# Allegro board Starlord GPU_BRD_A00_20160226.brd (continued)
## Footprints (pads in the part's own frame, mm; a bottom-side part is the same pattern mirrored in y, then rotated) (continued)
SOT23-2D4-312H44
  custom 0.191x0.191 smd: 1(-0.984,-0.953) 2(0.984,-0.953) 3(0,0.953)
SOT23-2D4-312H48
  custom 0.191x0.191 smd: 1(-0.984,-0.953) 2(0.984,-0.953) 3(0,0.953)
SOT23DGS2D4H44
  custom 0.191x0.191 smd: D(0,0.953) G(-0.984,-0.953) S(0.984,-0.953)
SOT-363H44
  rect 0.406x1.016 smd: 1(-0.65,-0.94) 2(0,-0.94) 3(0.65,-0.94) 4(0.65,0.94) 5(0,0.94) 6(-0.65,0.94)
STFSR158R113H62
  round 0.254 hole 2.87 unplated: (0,0)
  custom 1.003x1.003 smd: 1(0,-1.822)
TPAD14-OP
  round 0.356 smd: 1(0,0)
unnamed
  round 1.016 smd: (0,0)
XBGCB5008
  round 0.254 hole 2.718 unplated: (0,0)
  round 0.254 hole 0.711 unplated: (5.143,-2.145) (5.143,2.105)
  rect 0.813x0.508 smd: A1(-3.805,2.165) A2(-3.805,1.365) A3(-3.805,0.565) A4(-3.805,-0.235) A5(-3.805,-1.035) A6(-3.805,-1.835) B1(-2.205,2.165) B2(-2.205,1.365) B3(-2.205,0.565) B4(-2.205,-0.235) B5(-2.205,-1.035) B6(-2.205,-1.835) C1(2.595,2.165) C2(2.595,1.365) C3(2.595,0.565) C4(2.595,-0.235) C5(2.595,-1.035) C6(2.595,-1.835) D2(4.195,1.365) D3(4.195,0.565) D4(4.195,-0.235) D5(4.195,-1.035) P1(-0.605,2.165) P2(0.995,2.165) P3(-0.605,-1.835) P4(0.995,-1.835)
  rect 0.762x0.508 smd: D1(4.169,2.165) D6(4.169,-1.835)
  custom 1.124x1.124 smd: N1(-1.905,0)
XBGCB5009
  round 0.254 hole 0.711 unplated: (-5.325,-3.465) (0,3.34)
  round 0.254 hole 2.718 unplated: (0,0)
  rect 0.813x0.356 smd: A1(-4.15,2.845) A2(-4.15,2.245) A3(-4.15,1.645) A4(-4.15,1.045) A5(-4.15,0.445) A6(-4.15,-0.155) A7(-4.15,-0.755) A8(-4.15,-1.355) A9(-4.15,-1.955) A10(-4.15,-2.555) B1(-2.45,2.845) B2(-2.45,2.245) B3(-2.45,1.645) B4(-2.45,1.045) B5(-2.45,0.445) B6(-2.45,-0.155) B7(-2.45,-0.755) B8(-2.45,-1.355) B9(-2.45,-1.955) B10(-2.45,-2.555) C2(-0.82,2.245) C9(-0.82,-1.955) C10(-0.82,-2.555) D1(0.87,2.845) D2(0.87,2.245) D9(0.87,-1.955) D10(0.87,-2.555) E1(2.45,2.845) E2(2.45,2.245) E3(2.45,1.645) E4(2.45,1.045) E5(2.45,0.445) E6(2.45,-0.155) E7(2.45,-0.755) E8(2.45,-1.355) E9(2.45,-1.955) E10(2.45,-2.555) F1(4.15,2.845) F2(4.15,2.245) F3(4.15,1.645) F4(4.15,1.045) F5(4.15,0.445) F6(4.15,-0.155) F7(4.15,-0.755) F8(4.15,-1.355) F9(4.15,-1.955) F10(4.15,-2.555)
  rect 0.762x0.356 smd: C1(-0.846,2.845)
  custom 1.124x1.124 smd: N1(-1.905,0)

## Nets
3V3_AON_CT_2: C8306.1 U8301.10
3V3_AON_S0: C7315.1 C7316.1 C7324.1 C7704.1 C7735.1 C7736.1 C8301.1 GPU1.AA8 GPU1.AA9 GPU1.AB8 GPU1.G10 GPU1.G12 PR8203.1 PR8258.1 PR8304.1 PR8311.1 PR8316.1 Q7301.G Q7602.2 Q7606.G R7303.2 R7312.1 R7609.1 R7612.2 R7614.1 R7617.1 R7619.1 R7625.1 R7628.1 R7631.1 R7633.1 R7643.2 R7645.1 R7649.2 R7657.1 R8301.1 RN7601.3(B) RN7601.4(B) RN7604.1(A) RN7604.2(A) RN7605.1(A) RN7605.2(A) U7301.5 U8301.8 U8301.9
3V3_AON_S0_DISCHG: PQ8306.3 PR8316.2
5V_S0: GPU2.P2 PR8223.1 U8301.4
GND: C7310.2 C7312.2 C7315.2 C7316.2 C7317.2 C7318.2 C7319.2 C7323.2 C7324.2 C7326.2 C7501.2 C7502.2 C7505.2 C7506.2 C7507.2 C7513.2 C7514.2 C7517.2 C7518.2 C7520.2 C7525.2 C7601.2 C7602.2 C7603.2 C7604.2 C7605.2 C7606.2 C7607.1 C7608.1 C7609.2 C7610.2 C7701.2 C7702.2 C7703.2 C7704.2 C7708.2 C7709.2 C7710.2 C7711.2 C7712.2 C7713.2 C7714.2 C7717.2 C7719.2 C7720.2 C7721.2 C7722.2 C7723.2 C7724.2 C7725.2 C7726.2 C7728.2 C7729.2 C7730.2 C7731.2 C7732.2 C7734.2 C7735.2 C7736.2 C7801.1 C7802.2 C7803.2 C7804.2 C7805.2 C7806.2 C7807.2 C7808.2 C7809.2 C7810.2 C7811.2 C7812.2 C7813.2 C7814.2 C7815.2 C7816.2 C7817.2 C7818.2 C7819.2 C7820.2 C7821.2 C7822.2 C7823.2 C7824.2 C7825.2 C7826.2 C7901.1 C7902.2 C7903.2 C7904.2 C7905.2 C7906.2 C7907.2 C7908.2 C7909.2 C7910.2 C7911.2 C7912.2 C7913.2 C7914.2 C7915.2 C7916.2 C7917.2 C7918.2 C7919.2 C7920.2 C7921.2 C7922.2 C7923.2 C7924.2 C7925.2 C7926.2 C8301.2 C8302.2 C8304.2 C8305.2 C8306.2 C8307.2 C8308.1 C8309.2 C8310.2 EC9701.2 EC9702.2 EC9703.2 EC9704.2 EC9705.2 EC9706.2 GPU1.A2 GPU1.A26 GPU1.AA7 GPU1.AB7 GPU1.AB11 GPU1.AB14 GPU1.AB17 GPU1.AB20 GPU1.AB24 GPU1.AC2 GPU1.AC5 GPU1.AC8 GPU1.AC22 GPU1.AC26 GPU1.AD12 GPU1.AD13 GPU1.AD15 GPU1.AD16 GPU1.AD18 GPU1.AD19 GPU1.AD21 GPU1.AD22 GPU1.AE11 GPU1.AE14 GPU1.AE17 GPU1.AE20 GPU1.AF1 GPU1.AF5 GPU1.AF8 GPU1.AF11 GPU1.AF14 GPU1.AF17 GPU1.AF20 GPU1.AF23 GPU1.AG2 GPU1.AG26 GPU1.B1 GPU1.B5 GPU1.B8 GPU1.B11 GPU1.B14 GPU1.B17 GPU1.B20 GPU1.B23 GPU1.B27 GPU1.E2 GPU1.E5 GPU1.E8 GPU1.E11 GPU1.E14 GPU1.E17 GPU1.E20 GPU1.E22 GPU1.E25 GPU1.H2 GPU1.H5 GPU1.H23 GPU1.H25 GPU1.K11 GPU1.K13 GPU1.K15 GPU1.K17 GPU1.L2 GPU1.L5 GPU1.L10 GPU1.L12 GPU1.L14 GPU1.L16 GPU1.L18 GPU1.L23 GPU1.L25 GPU1.M11 GPU1.M13 GPU1.M15 GPU1.M17 GPU1.N10 GPU1.N12 GPU1.N14 GPU1.N16 GPU1.N18 GPU1.P2 GPU1.P5 GPU1.P11 GPU1.P13 GPU1.P15 GPU1.P17 GPU1.P23 GPU1.P26 GPU1.R10 GPU1.R12 GPU1.R14 GPU1.R16 GPU1.R18 GPU1.T11 GPU1.T13 GPU1.T15 GPU1.T17 GPU1.U2 GPU1.U5 GPU1.U10 GPU1.U12 GPU1.U14 GPU1.U16 GPU1.U18 GPU1.U23 GPU1.U26 GPU1.V11 GPU1.V13 GPU1.V15 GPU1.V17 GPU1.Y2 GPU1.Y5 GPU1.Y23 GPU1.Y26 GPU2.C1 GPU2.C2 GPU2.C3 GPU2.C4 GPU2.C5 GPU2.C6 GPU2.D1 GPU2.D2 GPU2.D3 GPU2.D4 GPU2.D5 GPU2.D6 GPU3.A2 GPU3.A5 GPU3.A8 GPU3.B1 GPU3.B4 GPU3.B7 GPU3.B10 GPU3.E1 GPU3.E4 GPU3.E7 GPU3.E10 GPU3.F2 GPU3.F5 GPU3.F8 H1.1 H2.1 H3.1 H4.1 H5.1 PC8202.1 PC8203.1 PC8205.2 PC8206.2 PC8207.2 PC8208.2 PC8209.2 PC8210.2 PC8212.2 PC8213.2 PC8214.2 PC8215.2 PC8217.2 PC8218.2 PC8220.1 PC8221.1 PC8222.2 PC8224.2 PC8225.1 PC8226.1 PC8301.2 PC8302.2 PC8303.2 PC8304.2 PC8306.2 PC8307.2 PC8309.2 PC8310.2 PC8311.2 PC8313.2 PC8314.2 PC8315.2 PC8316.2 PC8317.2 PC8318.2 PC8320.2 PC8321.2 PQ8301.1 PQ8301.4 PQ8305.1 PQ8305.4 PQ8306.1 PQ8306.4 PQ8307.1 PQ8307.4 PQ8308.1 PQ8308.4 PR8213.2 PR8224.2 PR8259.2 PR8302.2 PR8313.2 PR8323.1 PR8326.2 PT8206.2 PT8207.2 PT8208.2 PU8201.21 PU8202.5 PU8202.6 PU8202.7 PU8204.5 PU8204.6 PU8204.7 PU8206.5 PU8206.6 PU8206.7 PU8208.5 PU8208.6 PU8208.7 PU8301.11 PU8302.7 PU8302.8 PU8302.18 PU8302.21 Q7801.S Q7901.S R7301.2 R7302.2 R7306.2 R7506.2 R7507.1 R7518.2 R7520.1 R7521.1 R7601.2 R7602.2 R7606.2 R7607.1 R7608.2 R7610.2 R7611.2 R7615.2 R7616.2 R7621.2 R7622.2 R7624.2 R7626.2 R7627.2 R7629.2 R7632.2 R7637.2 R7807.2 R7808.2 R7809.2 R7810.1 R7811.1 R7813.2 R7901.2 R7904.2 R7909.1 R7911.1 R7912.2 R7913.2 R8304.2 RN301.3(B) RN301.4(B) RN7602.1(A) RN7602.2(A) U7301.3 U8301.11 U8301.15 VRAM1.A1 VRAM1.A3 VRAM1.A12 VRAM1.A14 VRAM1.B5 VRAM1.B10 VRAM1.C1 VRAM1.C3 VRAM1.C4 VRAM1.C11 VRAM1.C12 VRAM1.C13 VRAM1.C14 VRAM1.D10 VRAM1.E1 VRAM1.E3 VRAM1.E12 VRAM1.E14 VRAM1.F5 VRAM1.F10 VRAM1.G5 VRAM1.G10 VRAM1.H1 VRAM1.H2 VRAM1.H13 VRAM1.H14 VRAM1.K1 VRAM1.K2 VRAM1.K13 VRAM1.K14 VRAM1.L5 VRAM1.L10 VRAM1.M5 VRAM1.M10 VRAM1.N1 VRAM1.N3 VRAM1.N12 VRAM1.N14 VRAM1.P10 VRAM1.R1 VRAM1.R3 VRAM1.R4 VRAM1.R11 VRAM1.R12 VRAM1.R14 VRAM1.T5 VRAM1.T10 VRAM1.U1 VRAM1.U3 VRAM1.U12 VRAM1.U14 VRAM2.A1 VRAM2.A3 VRAM2.A12 VRAM2.A14 VRAM2.B5 VRAM2.B10 VRAM2.C1 VRAM2.C3 VRAM2.C4 VRAM2.C11 VRAM2.C12 VRAM2.C13 VRAM2.C14 VRAM2.D10 VRAM2.E1 VRAM2.E3 VRAM2.E12 VRAM2.E14 VRAM2.F5 VRAM2.F10 VRAM2.G5 VRAM2.G10 VRAM2.H1 VRAM2.H2 VRAM2.H13 VRAM2.H14 VRAM2.K1 VRAM2.K2 VRAM2.K13 VRAM2.K14 VRAM2.L5 VRAM2.L10 VRAM2.M5 VRAM2.M10 VRAM2.N1 VRAM2.N3 VRAM2.N12 VRAM2.N14 VRAM2.P10 VRAM2.R1 VRAM2.R3 VRAM2.R4 VRAM2.R11 VRAM2.R12 VRAM2.R14 VRAM2.T5 VRAM2.T10 VRAM2.U1 VRAM2.U3 VRAM2.U12 VRAM2.U14 VRAM3.A1 VRAM3.A3 VRAM3.A12 VRAM3.A14 VRAM3.B5 VRAM3.B10 VRAM3.C1 VRAM3.C3 VRAM3.C4 VRAM3.C11 VRAM3.C12 VRAM3.C13 VRAM3.C14 VRAM3.D10 VRAM3.E1 VRAM3.E3 VRAM3.E12 VRAM3.E14 VRAM3.F5 VRAM3.F10 VRAM3.G5 VRAM3.G10 VRAM3.H1 VRAM3.H2 VRAM3.H13 VRAM3.H14 VRAM3.K1 VRAM3.K2 VRAM3.K13 VRAM3.K14 VRAM3.L5 VRAM3.L10 VRAM3.M5 VRAM3.M10 VRAM3.N1 VRAM3.N3 VRAM3.N12 VRAM3.N14 VRAM3.P10 VRAM3.R1 VRAM3.R3 VRAM3.R4 VRAM3.R11 VRAM3.R12 VRAM3.R14 VRAM3.T5 VRAM3.T10 VRAM3.U1 VRAM3.U3 VRAM3.U12 VRAM3.U14 VRAM4.A1 VRAM4.A3 VRAM4.A12 VRAM4.A14 VRAM4.B5 VRAM4.B10 VRAM4.C1 VRAM4.C3 VRAM4.C4 VRAM4.C11 VRAM4.C12 VRAM4.C13 VRAM4.C14 VRAM4.D10 VRAM4.E1 VRAM4.E3 VRAM4.E12 VRAM4.E14 VRAM4.F5 VRAM4.F10 VRAM4.G5 VRAM4.G10 VRAM4.H1 VRAM4.H2 VRAM4.H13 VRAM4.H14 VRAM4.K1 VRAM4.K2 VRAM4.K13 VRAM4.K14 VRAM4.L5 VRAM4.L10 VRAM4.M5 VRAM4.M10 VRAM4.N1 VRAM4.N3 VRAM4.N12 VRAM4.N14 VRAM4.P10 VRAM4.R1 VRAM4.R3 VRAM4.R4 VRAM4.R11 VRAM4.R12 VRAM4.R14 VRAM4.T5 VRAM4.T10 VRAM4.U1 VRAM4.U3 VRAM4.U12 VRAM4.U14 X7601.2 X7601.4
VCC1R05VIDEO_PEX_PLLVDD: C7317.1 C7318.1 C7319.1 GPU1.AA14 GPU1.AA15 L7301.1
1D05V_PWR: PC8303.1 PC8304.1 PC8305.1 PG8304.2 PG8305.2 PG8306.2 PG8307.2 PL8301.2 PR8303.1
1D05V_VGA_EN: C8308.2 PQ8301.2 PR8308.1 PR8310.2 R8305.2
1D05V_VGA_EN#: PQ8301.5 PQ8301.6 PR8307.2
1D05V_VGA_S0: C7310.1 C7312.1 C7323.1 C7326.1 GPU1.AA10 GPU1.AA12 GPU1.AA13 GPU1.AA16 GPU1.AA18 GPU1.AA19 GPU1.AA20 GPU1.AA21 GPU1.AA22 GPU1.AB22 GPU1.AB23 GPU1.AC23 GPU1.AC24 GPU1.AD24 GPU1.AD25 GPU1.AE25 GPU1.AE26 GPU1.AE27 GPU1.AF26 GPU1.AF27 L7301.2 L7501.2 L7601.1 L7602.1 PG8304.1 PG8305.1 PG8306.1 PG8307.1 PR8306.1
1D05V_VGA_S0_DISCHG: PQ8301.3 PR8306.2
1D05V_VGA_S0_PWRGD: D8301.2 PR8320.2 R8303.1
1D35V_PGOOD: PR8321.1 TP8301.1
1D35V_PWR: PC8311.1 PC8313.1 PC8314.1 PC8320.1 PC8321.1 PG8308.1 PG8309.1 PG8310.1 PG8311.1 PG8312.1 PG8313.1 PG8318.1 PG8319.1 PG8320.1 PL8302.2
1D35V_VGA_EN: D8301.3 PQ8308.2 PR8322.1 R8303.2 R8304.1
1D35V_VGA_EN#: PQ8308.5 PQ8308.6 PR8328.1
1D35V_VGA_S0: C7501.1 C7502.1 C7507.1 C7513.1 C7514.1 C7517.1 C7520.1 C7525.1 C7804.1 C7805.1 C7806.1 C7807.1 C7808.1 C7809.1 C7810.1 C7811.1 C7812.1 C7813.1 C7814.1 C7815.1 C7816.1 C7817.1 C7818.1 C7819.1 C7820.1 C7821.1 C7822.1 C7823.1 C7824.1 C7825.1 C7904.1 C7905.1 C7906.1 C7907.1 C7909.1 C7910.1 C7911.1 C7912.1 C7913.1 C7914.1 C7915.1 C7916.1 C7917.1 C7918.1 C7919.1 C7920.1 C7921.1 C7922.1 C7923.1 C7924.1 C7925.1 C7926.1 GPU1.B26 GPU1.C25 GPU1.E23 GPU1.E26 GPU1.F14 GPU1.F21 GPU1.G13 GPU1.G14 GPU1.G15 GPU1.G16 GPU1.G18 GPU1.G19 GPU1.G20 GPU1.G21 GPU1.H24 GPU1.H26 GPU1.J21 GPU1.K21 GPU1.L22 GPU1.L24 GPU1.L26 GPU1.M21 GPU1.N21 GPU1.R21 GPU1.T21 GPU1.V21 GPU1.W21 PG8308.2 PG8309.2 PG8310.2 PG8311.2 PG8312.2 PG8318.2 PG8319.2 PG8320.2 R7501.2 R7503.2 R7505.2 R7516.2 R7524.2 R7805.1 R7806.1 R7812.2 R7903.1 R7907.1 R7910.2 VRAM1.B1 VRAM1.B3 VRAM1.B12 VRAM1.B14 VRAM1.C5 VRAM1.C10 VRAM1.D1 VRAM1.D3 VRAM1.D11 VRAM1.D12 VRAM1.D14 VRAM1.E5 VRAM1.E10 VRAM1.F1 VRAM1.F3 VRAM1.F12 VRAM1.F14 VRAM1.G1 VRAM1.G2 VRAM1.G4 VRAM1.G11 VRAM1.G13 VRAM1.G14 VRAM1.H3 VRAM1.H12 VRAM1.K3 VRAM1.K12 VRAM1.L1 VRAM1.L2 VRAM1.L4 VRAM1.L11 VRAM1.L13 VRAM1.L14 VRAM1.M1 VRAM1.M3 VRAM1.M12 VRAM1.M14 VRAM1.N5 VRAM1.N10 VRAM1.P1 VRAM1.P3 VRAM1.P11 VRAM1.P12 VRAM1.P14 VRAM1.R5 VRAM1.R10 VRAM1.T1 VRAM1.T3 VRAM1.T12 VRAM1.T14 VRAM2.B1 VRAM2.B3 VRAM2.B12 VRAM2.B14 VRAM2.C5 VRAM2.C10 VRAM2.D1 VRAM2.D3 VRAM2.D11 VRAM2.D12 VRAM2.D14 VRAM2.E5 VRAM2.E10 VRAM2.F1 VRAM2.F3 VRAM2.F12 VRAM2.F14 VRAM2.G1 VRAM2.G2 VRAM2.G4 VRAM2.G11 VRAM2.G13 VRAM2.G14 VRAM2.H3 VRAM2.H12 VRAM2.K3 VRAM2.K12 VRAM2.L1 VRAM2.L2 VRAM2.L4 VRAM2.L11 VRAM2.L13 VRAM2.L14 VRAM2.M1 VRAM2.M3 VRAM2.M12 VRAM2.M14 VRAM2.N5 VRAM2.N10 VRAM2.P1 VRAM2.P3 VRAM2.P11 VRAM2.P12 VRAM2.P14 VRAM2.R5 VRAM2.R10 VRAM2.T1 VRAM2.T3 VRAM2.T12 VRAM2.T14 VRAM3.B1 VRAM3.B3 VRAM3.B12 VRAM3.B14 VRAM3.C5 VRAM3.C10 VRAM3.D1 VRAM3.D3 VRAM3.D11 VRAM3.D12 VRAM3.D14 VRAM3.E5 VRAM3.E10 VRAM3.F1 VRAM3.F3 VRAM3.F12 VRAM3.F14 VRAM3.G1 VRAM3.G2 VRAM3.G4 VRAM3.G11 VRAM3.G13 VRAM3.G14 VRAM3.H3 VRAM3.H12 VRAM3.K3 VRAM3.K12 VRAM3.L1 VRAM3.L2 VRAM3.L4 VRAM3.L11 VRAM3.L13 VRAM3.L14 VRAM3.M1 VRAM3.M3 VRAM3.M12 VRAM3.M14 VRAM3.N5 VRAM3.N10 VRAM3.P1 VRAM3.P3 VRAM3.P11 VRAM3.P12 VRAM3.P14 VRAM3.R5 VRAM3.R10 VRAM3.T1 VRAM3.T3 VRAM3.T12 VRAM3.T14 VRAM4.B1 VRAM4.B3 VRAM4.B12 VRAM4.B14 VRAM4.C5 VRAM4.C10 VRAM4.D1 VRAM4.D3 VRAM4.D11 VRAM4.D12 VRAM4.D14 VRAM4.E5 VRAM4.E10 VRAM4.F1 VRAM4.F3 VRAM4.F12 VRAM4.F14 VRAM4.G1 VRAM4.G2 VRAM4.G4 VRAM4.G11 VRAM4.G13 VRAM4.G14 VRAM4.H3 VRAM4.H12 VRAM4.K3 VRAM4.K12 VRAM4.L1 VRAM4.L2 VRAM4.L4 VRAM4.L11 VRAM4.L13 VRAM4.L14 VRAM4.M1 VRAM4.M3 VRAM4.M12 VRAM4.M14 VRAM4.N5 VRAM4.N10 VRAM4.P1 VRAM4.P3 VRAM4.P11 VRAM4.P12 VRAM4.P14 VRAM4.R5 VRAM4.R10 VRAM4.T1 VRAM4.T3 VRAM4.T12 VRAM4.T14
1D35V_VGA_S0_DISCHG: PQ8308.3 PR8329.2
3D3V_AUX_S5: GPU3.F10 PR8307.1 PR8315.2 PR8317.2 PR8319.2 PR8328.2
3D3V_S0: C8305.1 C8307.1 GPU2.P1 GPU2.P3 GPU2.P4 PG8301.2 PG8302.2 PG8303.2 PR8325.2 R7648.2 U8301.1 U8301.2 U8301.6 U8301.7
3D3V_VGA_CT_1: C8302.1 U8301.12
3D3V_VGA_S0: C7703.1 C7728.1 C7729.1 C7734.1 C8304.1 GPU1.G8 GPU1.G9 PR8256.1 PR8310.1 PR8318.1 PR8329.1 R7605.1 R7618.1 R7620.1 R7635.1 R8301.2 U8301.13 U8301.14
3D3V_VGA_S0_DISCHG: PQ8307.3 PR8318.2
27MHZ_IN: C7607.2 GPU1.C11 R7603.1 X7601.1
27MHZ_OUT: GPU1.B10 R7603.2 R7604.2
27MHZ_OUT_R: C7608.2 R7604.1 X7601.3
AC_PRESENT: D7601.K TP7608.1
CLK_PCIE_VGA: GPU1.AE8 GPU3.B3
CLK_PCIE_VGA#: GPU1.AD8 GPU3.B2
CLKREQ_PEG#0: GPU3.A9 Q7301.D R7305.1
CPU_RXN_C_DGPU_TXN0: C7302.1 GPU3.E8
CPU_RXN_C_DGPU_TXN1: C7304.1 GPU3.E5
CPU_RXN_C_DGPU_TXN2: C7306.1 GPU3.F6
CPU_RXN_C_DGPU_TXN3: C7308.1 GPU3.F3
CPU_RXP_C_DGPU_TXP0: C7301.1 GPU3.E9
CPU_RXP_C_DGPU_TXP1: C7303.1 GPU3.E6
CPU_RXP_C_DGPU_TXP2: C7305.1 GPU3.F7
CPU_RXP_C_DGPU_TXP3: C7307.1 GPU3.F4
DCBATOUT: EC9701.1 EC9702.1 EC9703.1 EC9704.1 EC9705.1 EC9706.1 GPU2.A1 GPU2.A2 GPU2.A3 GPU2.A4 GPU2.A5 GPU2.A6 GPU2.B1 GPU2.B2 GPU2.B3 GPU2.B4 GPU2.B5 GPU2.B6 PC8208.1 PC8209.1 PC8210.1 PC8212.1 PC8213.1 PC8214.1 PC8215.1 PC8220.2 PC8221.2 PC8224.1 PG8314.1 PG8315.1 PG8316.1 PG8317.1 PR8202.1 PU8202.2 PU8202.3 PU8202.4 PU8202.10 PU8204.2 PU8204.3 PU8204.4 PU8204.10 PU8206.2 PU8206.3 PU8206.4 PU8206.10 PU8208.2 PU8208.3 PU8208.4 PU8208.10
DGPU_HOLD_RST#: GPU3.D1 R7304.1 U7301.1
DGPU_PWR_EN: GPU3.C1 PQ8306.2 PR8260.1 PR8331.1
DGPU_PWR_EN#: PQ8306.5 PQ8306.6 PR8317.1
DGPU_PWR_EN_R: C8310.1 PR8331.2 R8306.1 U8301.5
DGPU_PWROK: GPU3.D2 PR8203.2 PU8201.13 R8305.1
DGPU_RXN_C_CPU_TXN0: GPU1.AG7 GPU3.A6
DGPU_RXN_C_CPU_TXN1: GPU1.AE7 GPU3.A3
DGPU_RXN_C_CPU_TXN2: GPU1.AF9 GPU3.B8
DGPU_RXN_C_CPU_TXN3: GPU1.AG10 GPU3.B5
DGPU_RXP_C_CPU_TXP0: GPU1.AG6 GPU3.A7
DGPU_RXP_C_CPU_TXP1: GPU1.AF7 GPU3.A4
DGPU_RXP_C_CPU_TXP2: GPU1.AE9 GPU3.B9
DGPU_RXP_C_CPU_TXP3: GPU1.AG9 GPU3.B6
DGPU_TXN_CPU_RXN0: C7302.2 GPU1.AB9
DGPU_TXN_CPU_RXN1: C7304.2 GPU1.AC10
DGPU_TXN_CPU_RXN2: C7306.2 GPU1.AC11
DGPU_TXN_CPU_RXN3: C7308.2 GPU1.AB12
DGPU_TXP_CPU_RXP0: C7301.2 GPU1.AC9
DGPU_TXP_CPU_RXP1: C7303.2 GPU1.AB10
DGPU_TXP_CPU_RXP2: C7305.2 GPU1.AD11
DGPU_TXP_CPU_RXP3: C7307.2 GPU1.AC12
FB_CAL_PD_VDDQ: GPU1.D22 R7505.1
FB_CAL_PU_GND: GPU1.C24 R7507.2
FB_CAL_TERM_GND: GPU1.B25 R7506.1
FB_CLAM: GPU1.F3 R7518.1 R7519.1
FB_VREF: GPU1.D23 TP7503.1
FBA_CLK0_MIDPT: C7801.2 R7801.2 R7802.2
FBA_CLK0N: GPU1.D25 R7802.1 VRAM1.J11 VRAM2.J11
FBA_CLK0P: GPU1.D24 R7801.1 VRAM1.J12 VRAM2.J12
FBA_CLK1_MIDPT: C7901.2 R7906.2 R7908.2
FBA_CLK1N: GPU1.M22 R7906.1 VRAM3.J11 VRAM4.J11
FBA_CLK1P: GPU1.N22 R7908.1 VRAM3.J12 VRAM4.J12
FBA_CMD0: GPU1.C27 VRAM1.G12 VRAM2.L12
FBA_CMD1: GPU1.C26 VRAM1.H10 VRAM2.K10
FBA_CMD2: GPU1.E24 VRAM1.H11 VRAM2.K11
FBA_CMD3: GPU1.F24 VRAM1.K11 VRAM2.H11
FBA_CMD4: GPU1.D27 VRAM1.K10 VRAM2.H10
FBA_CMD5: GPU1.D26 VRAM1.L12 VRAM2.G12
FBA_CMD6: GPU1.F25 VRAM1.K4 VRAM2.H4
FBA_CMD7: GPU1.F26 VRAM1.K5 VRAM2.H5
FBA_CMD8: GPU1.F23 VRAM1.J4 VRAM2.J4
FBA_CMD9: GPU1.G22 VRAM1.J5 VRAM2.J5
FBA_CMD10: GPU1.G23 VRAM1.H4 VRAM2.K4
FBA_CMD11: GPU1.G24 VRAM1.H5 VRAM2.K5
FBA_CMD12: GPU1.F27 VRAM1.G3 VRAM2.L3
FBA_CMD13: GPU1.G25 R7520.2 VRAM1.J2 VRAM2.J2
FBA_CMD14: GPU1.G27 R7516.1 VRAM1.J3 VRAM2.J3
FBA_CMD15: GPU1.G26 VRAM1.L3 VRAM2.G3
FBA_CMD16: GPU1.M24 VRAM3.G12 VRAM4.L12
FBA_CMD17: GPU1.M23 VRAM3.H10 VRAM4.K10
FBA_CMD18: GPU1.K24 VRAM3.H11 VRAM4.K11
FBA_CMD19: GPU1.K23 VRAM3.K11 VRAM4.H11
FBA_CMD20: GPU1.M27 VRAM3.K10 VRAM4.H10
FBA_CMD21: GPU1.M26 VRAM3.L12 VRAM4.G12
FBA_CMD22: GPU1.M25 VRAM3.K4 VRAM4.H4
FBA_CMD23: GPU1.K26 VRAM3.K5 VRAM4.H5
FBA_CMD24: GPU1.K22 VRAM3.J4 VRAM4.J4
FBA_CMD25: GPU1.J23 VRAM3.J5 VRAM4.J5
FBA_CMD26: GPU1.J25 VRAM3.H4 VRAM4.K4
FBA_CMD27: GPU1.J24 VRAM3.H5 VRAM4.K5
FBA_CMD28: GPU1.K27 VRAM3.G3 VRAM4.L3
FBA_CMD29: GPU1.K25 R7521.2 VRAM3.J2 VRAM4.J2
FBA_CMD30: GPU1.J27 R7524.1 VRAM3.J3 VRAM4.J3
FBA_CMD31: GPU1.J26 VRAM3.L3 VRAM4.G3
FBA_D0: GPU1.E18 VRAM1.A4
FBA_D1: GPU1.F18 VRAM1.A2
FBA_D2: GPU1.E16 VRAM1.B4
FBA_D3: GPU1.F17 VRAM1.B2
FBA_D4: GPU1.D20 VRAM1.E4
FBA_D5: GPU1.D21 VRAM1.E2
FBA_D6: GPU1.F20 VRAM1.F4
FBA_D7: GPU1.E21 VRAM1.F2
FBA_D8: GPU1.E15 VRAM2.U11
FBA_D9: GPU1.D15 VRAM2.U13
FBA_D10: GPU1.F15 VRAM2.T11
FBA_D11: GPU1.F13 VRAM2.T13
FBA_D12: GPU1.C13 VRAM2.N11
FBA_D13: GPU1.B13 VRAM2.N13
FBA_D14: GPU1.E13 VRAM2.M11
FBA_D15: GPU1.D13 VRAM2.M13
FBA_D16: GPU1.B15 VRAM1.U11
FBA_D17: GPU1.C16 VRAM1.U13
FBA_D18: GPU1.A13 VRAM1.T11
FBA_D19: GPU1.A15 VRAM1.T13
FBA_D20: GPU1.B18 VRAM1.N11
FBA_D21: GPU1.A18 VRAM1.N13
FBA_D22: GPU1.A19 VRAM1.M11
FBA_D23: GPU1.C19 VRAM1.M13
FBA_D24: GPU1.B24 VRAM2.A4
FBA_D25: GPU1.C23 VRAM2.A2
FBA_D26: GPU1.A25 VRAM2.B4
FBA_D27: GPU1.A24 VRAM2.B2
FBA_D28: GPU1.A21 VRAM2.E4
FBA_D29: GPU1.B21 VRAM2.E2
FBA_D30: GPU1.C20 VRAM2.F4
FBA_D31: GPU1.C21 VRAM2.F2
FBA_D32: GPU1.R22 VRAM3.A4
FBA_D33: GPU1.R24 VRAM3.A2
FBA_D34: GPU1.T22 VRAM3.B4
FBA_D35: GPU1.R23 VRAM3.B2
FBA_D36: GPU1.N25 VRAM3.E4
FBA_D37: GPU1.N26 VRAM3.E2
FBA_D38: GPU1.N23 VRAM3.F4
FBA_D39: GPU1.N24 VRAM3.F2
FBA_D40: GPU1.V23 VRAM4.U11
FBA_D41: GPU1.V22 VRAM4.U13
FBA_D42: GPU1.T23 VRAM4.T11
FBA_D43: GPU1.U22 VRAM4.T13
FBA_D44: GPU1.Y24 VRAM4.N11
FBA_D45: GPU1.AA24 VRAM4.N13
FBA_D46: GPU1.Y22 VRAM4.M11
FBA_D47: GPU1.AA23 VRAM4.M13
FBA_D48: GPU1.AD27 VRAM3.U11
FBA_D49: GPU1.AB25 VRAM3.U13
FBA_D50: GPU1.AD26 VRAM3.T11
FBA_D51: GPU1.AC25 VRAM3.T13
FBA_D52: GPU1.AA27 VRAM3.N11
FBA_D53: GPU1.AA26 VRAM3.N13
FBA_D54: GPU1.W26 VRAM3.M11
FBA_D55: GPU1.Y25 VRAM3.M13
FBA_D56: GPU1.R26 VRAM4.A4
FBA_D57: GPU1.T25 VRAM4.A2
FBA_D58: GPU1.N27 VRAM4.B4
FBA_D59: GPU1.R27 VRAM4.B2
FBA_D60: GPU1.V26 VRAM4.E4
FBA_D61: GPU1.V27 VRAM4.E2
FBA_D62: GPU1.W27 VRAM4.F4
FBA_D63: GPU1.W25 VRAM4.F2
FBA_DEBUG0: GPU1.F22 R7501.1
FBA_DEBUG1: GPU1.J22 R7503.1
FBA_DQM0: GPU1.D19 VRAM1.D2
FBA_DQM1: GPU1.D14 VRAM2.P13
FBA_DQM2: GPU1.C17 VRAM1.P13
FBA_DQM3: GPU1.C22 VRAM2.D2
FBA_DQM4: GPU1.P24 VRAM3.D2
FBA_DQM5: GPU1.W24 VRAM4.P13
FBA_DQM6: GPU1.AA25 VRAM3.P13
FBA_DQM7: GPU1.U25 VRAM4.D2
FBA_EDC0: GPU1.E19 VRAM1.C2
FBA_EDC1: GPU1.C15 VRAM2.R13
FBA_EDC2: GPU1.B16 VRAM1.R13
FBA_EDC3: GPU1.B22 VRAM2.C2
FBA_EDC4: GPU1.R25 VRAM3.C2
FBA_EDC5: GPU1.W23 VRAM4.R13
FBA_EDC6: GPU1.AB26 VRAM3.R13
FBA_EDC7: GPU1.T26 VRAM4.C2
FBA_MF1: R7811.2 VRAM1.J1
FBA_MF2: R7812.1 VRAM2.J1
FBA_MF3: R7911.2 VRAM3.J1
FBA_MF4: R7910.1 VRAM4.J1
FBA_PLL_AVDD: C7505.1 C7506.1 C7518.1 GPU1.F16 GPU1.H22 GPU1.P22 L7501.1
FBA_SEN0: R7810.2 VRAM1.J10 VRAM2.J10
FBA_SEN2: R7909.2 VRAM3.J10 VRAM4.J10
FBA_VREF_FET_H: Q7901.D R7902.2 R7905.2
FBA_VREF_FET_L: Q7801.D R7803.2 R7804.2
FBA_VREFC0: C7803.1 R7804.1 R7806.2 R7807.1 VRAM1.J14 VRAM2.J14
FBA_VREFC1: C7902.1 R7902.1 R7903.2 R7904.1 VRAM3.J14 VRAM4.J14
FBA_VREFD_H: C7903.1 C7908.1 R7901.1 R7905.1 R7907.2 VRAM3.A10 VRAM3.U10 VRAM4.A10 VRAM4.U10
FBA_VREFD_L: C7802.1 C7826.1 R7803.1 R7805.2 R7809.1 VRAM1.A10 VRAM1.U10 VRAM2.A10 VRAM2.U10
FBA_WCK01: GPU1.D18 VRAM1.D4 VRAM2.P4
FBA_WCK01#: GPU1.C18 VRAM1.D5 VRAM2.P5
FBA_WCK23: GPU1.D17 VRAM1.P4 VRAM2.D4
FBA_WCK23#: GPU1.D16 VRAM1.P5 VRAM2.D5
FBA_WCK45: GPU1.T24 VRAM3.D4 VRAM4.P4
FBA_WCK45#: GPU1.U24 VRAM3.D5 VRAM4.P5
FBA_WCK67: GPU1.V24 VRAM3.P4 VRAM4.D4
FBA_WCK67#: GPU1.V25 VRAM3.P5 VRAM4.D5
FBA_ZQ0: R7808.1 VRAM1.J13
FBA_ZQ1: R7813.1 VRAM2.J13
FBA_ZQ2: R7912.1 VRAM3.J13
FBA_ZQ3: R7913.1 VRAM4.J13
GC6_FB_EN: D8301.1 GPU3.C10 R7519.2 R7623.1
GC6_FB_EN_GPU: GPU1.C6 R7623.2 R7627.1
GPIO5_GC6_PWR_EN: PQ8307.2 PR8330.1 R7636.2
GPIO5_GC6_PWR_EN#: PQ8307.5 PQ8307.6 PR8319.1
GPIO5_GC6_PWR_EN_GPU: GPU1.A3 R7633.2 R7636.1
GPIO5_GC6_PWR_EN_R: C8309.1 PR8330.2 R8306.2 U8301.3
GPIO9_ALERT: GPU1.F8 Q7602.1 R7612.1
GPIO10_FBVREF: GPU1.C5 Q7801.G Q7901.G R7610.1
GPU_CLKREQ#: GPU1.AC6 Q7301.S R7303.1 R7305.2
GPU_EVENT#: GPU3.F1 Q7606.D R7644.1 R7648.1
GPU_EVENT_GPU#: GPU1.A4 Q7606.S R7644.2 R7649.1
GPU_I2CA_SCL: GPU1.B7 RN301.1(A)
GPU_I2CA_SDA: GPU1.A7 RN301.2(A)
GPU_NC_F11: GPU1.F11 TP601.1
GPU_PEX_RST#: GPU1.AC7 Q7602.5 R7308.1 R7312.2 R7313.2 R7613.1
GPU_PEX_RST_D#: D7301.3 R7308.2
GPU_PEX_RST_HOLD: D7301.1 R7630.2 R7631.2
GPU_PEX_RST_HOLD_GPU#: GPU1.C4 R7630.1
GPU_PLL_VDD: C7605.1 C7606.1 GPU1.L6 L7601.2
GPU_ROM_SCLK: GPU1.C12 R7620.2 R7621.1
GPU_ROM_SI: GPU1.B12 R7606.1 R7616.1 R7622.1 R7624.1 R7635.2 R7637.1
GPU_ROM_SO: GPU1.A12 R7618.2 R7632.1
I2CB_SCL: GPU1.C9 RN7605.3(B)
I2CB_SDA: GPU1.C8 RN7605.4(B)
I2CC_SCL: GPU1.A9 RN7604.4(B)
I2CC_SDA: GPU1.B9 RN7604.3(B)
N12P_JTAG_TCK: GPU1.AE5 RN7602.3(B)
N12P_JTAG_TDI: GPU1.AE6 TP7605.1
N12P_JTAG_TDO: GPU1.AF6 TP7601.1
N12P_JTAG_TMS: GPU1.AD6 TP7602.1
N12P_JTAG_TRST: GPU1.AG4 RN7602.4(B)
N12P_XTAL_OUTBUFF: GPU1.C10 R7602.1 R7617.2
OVER_CURRENT_P8#: D7602.K GPU3.C9
OVERT#: C7609.1 Q7602.4 R7613.2 R7645.2 R7656.1
OVERT_GPU#: GPU1.A6 R7656.2
P2800_VGA_DXN: GPU1.E12 TP7603.1
P2800_VGA_DXP: GPU1.F12 TP7604.1
P_H_S#: Q7602.3 R7653.1
PEX_TERMP: GPU1.AF25 R7301.1
PEXTSTCLK_OUT: GPU1.AF22 R7307.1
PEXTSTCLK_OUT#: GPU1.AE22 R7307.2
PLT_RST#: GPU3.D10 U7301.2
PURE_HW_SHUTDOWN#: C7610.1 R7653.2 TP7607.1
PWR_1D05V_EN: PC8302.1 PR8308.2 PU8301.5
PWR_1D05V_FB: PC8305.2 PC8312.1 PR8302.1 PR8303.2 PU8301.6
PWR_1D05V_FB_R: PC8312.2 PR8313.1
PWR_1D05V_PGOOD: PR8304.2 PR8320.1 PU8301.4
PWR_1D05V_PHASE: PL8301.1 PU8301.1 PU8301.2 PU8301.3
PWR_1D05V_PVDD: PC8306.1 PC8307.1 PG8301.1 PG8302.1 PG8303.1 PR8301.1 PU8301.9 PU8301.10
PWR_1D05V_SVIN: PC8301.1 PR8301.2 PU8301.8
PWR_1D35V_BOOT: PR8324.1 PU8302.1
PWR_1D35V_BOOT_R: PC8319.1 PR8324.2
PWR_1D35V_BYP: PC8318.1 PR8325.1 PU8302.15
PWR_1D35V_EN: PC8316.1 PR8322.2 PU8302.11
PWR_1D35V_IMAX: PR8323.2 PU8302.13
PWR_1D35V_LDO_P5: PC8317.1 PU8302.16 PU8302.17
PWR_1D35V_PGOOD: PR8311.2 PR8321.2 PU8302.9 PU8302.10
PWR_1D35V_PHASE: PC8319.2 PL8302.1 PU8302.6 PU8302.19 PU8302.20
PWR_1D35V_VFB: PC8308.2 PR8326.1 PR8327.2 PU8302.14
PWR_1D35V_VFB1: PC8308.1 PG8313.2 PR8327.1
PWR_DCBATOUT_1D35V: PC8309.1 PC8310.1 PC8315.1 PG8314.2 PG8315.2 PG8316.2 PG8317.2 PU8302.2 PU8302.3 PU8302.4 PU8302.5
PWR_LEVEL: D7601.A D7602.A GPU1.D7 R7605.2
PWR_VGA_CORE_BOOT1: PR8210.1 PU8201.1
PWR_VGA_CORE_BOOT1_1: PC8211.1 PR8210.2
PWR_VGA_CORE_BOOT2: PR8211.1 PU8201.15
PWR_VGA_CORE_BOOT2_1: PC8216.1 PR8211.2
PWR_VGA_CORE_EN: PC8225.2 PQ8305.2 PR8256.2 PR8260.2 PU8201.3
PWR_VGA_CORE_EN#: PQ8305.5 PQ8305.6 PR8315.1
PWR_VGA_CORE_LGATE1: PR8224.1 PU8201.19 PU8202.8 PU8204.8
PWR_VGA_CORE_LGATE2: PU8201.17 PU8206.8 PU8208.8
PWR_VGA_CORE_PHASE1: PC8211.2 PL8201.1 PR8216.1 PU8201.20 PU8202.9 PU8204.9
PWR_VGA_CORE_PHASE2: PC8216.2 PL8202.1 PR8215.1 PU8201.16 PU8206.9 PU8208.9
PWR_VGA_CORE_PSI: PC8226.2 PR8257.2 PR8258.2 PR8259.1 PU8201.4
PWR_VGA_CORE_REFADJ: PR8222.1 PU8201.6
PWR_VGA_CORE_REFIN: PC8204.1 PR8208.1 PR8209.1 PU8201.7
PWR_VGA_CORE_RGND: PC8201.1 PC8204.2 PC8217.1 PC8219.2 PC8223.2 PR8209.2 PR8213.1 PR8220.1 PU8201.10
PWR_VGA_CORE_SS: PC8205.1 PU8201.11
PWR_VGA_CORE_TON: PR8201.2 PU8201.9
PWR_VGA_CORE_TON_1: PC8202.2 PR8201.1 PR8202.2
PWR_VGA_CORE_UGATE1: PU8201.2 PU8202.1 PU8204.1
PWR_VGA_CORE_UGATE2: PU8201.14 PU8206.1 PU8208.1
PWR_VGA_CORE_VID: PC8203.2 PR8207.2 PU8201.5
PWR_VGA_CORE_VREF: PC8201.2 PR8206.1 PU8201.8
PWR_VGA_CORE_VSNS: PC8219.1 PC8222.1 PR8212.2 PR8221.1 PU8201.12
PWR_VGA_SNUB1: PC8206.1 PR8216.2
PWR_VGA_SNUB2: PC8218.1 PR8215.2
Q7601_G: Q7601.2 Q7601.5 R7657.2
REFIN_VREF: PC8223.1 PR8206.2 PR8208.2 PR8222.2
RT8812_PVCC: PC8207.1 PR8223.2 PU8201.18
SMBC_THERM_NV: GPU1.D9 Q7601.1 RN7601.2(A)
SMBD_THERM_NV: GPU1.D8 Q7601.4 RN7601.1(A)
SML1_SMBCLK: GPU3.E3 Q7601.6
SML1_SMBDATA: GPU3.E2 Q7601.3
SP_PLLVDD: C7601.1 C7602.1 C7603.1 C7604.1 GPU1.M6 GPU1.N6 L7602.2
STRAP0: GPU1.D1 R7608.1 R7619.2
STRAP1: GPU1.D2 R7609.2 R7611.1
STRAP2: GPU1.E4 R7614.2 R7615.1
STRAP3: GPU1.E3 R7625.2 R7626.1
STRAP4: GPU1.D3 R7628.2 R7629.1
STRAP_REF0_GND_N9: GPU1.F6 R7607.2
SYS_PEX_RST_MON#: D7301.2 R7304.2 R7306.1 R7313.1 R7634.2 U7301.4
SYS_PEX_RST_MON_GPU#: GPU1.E9 R7634.1 R7643.1
TESTMODE: GPU1.AD9 R7302.1
TP_VPPNC3: TP7803.1 VRAM2.A5
TP_VPPNC4: TP7804.1 VRAM2.U5
TP_VPPNC5: TP7901.1 VRAM3.A5
TP_VPPNC6: TP7902.1 VRAM3.U5
TP_VPPNC7: TP7903.1 VRAM4.A5
TP_VPPNC8: TP7904.1 VRAM4.U5
VGA_CORE: C7701.1 C7702.1 C7708.1 C7709.1 C7710.1 C7711.1 C7712.1 C7713.1 C7714.1 C7717.1 C7719.1 C7720.1 C7721.1 C7722.1 C7723.1 C7724.1 C7725.1 C7726.1 C7730.1 C7731.1 C7732.1 GPU1.K10 GPU1.K12 GPU1.K14 GPU1.K16 GPU1.K18 GPU1.L11 GPU1.L13 GPU1.L15 GPU1.L17 GPU1.M10 GPU1.M12 GPU1.M14 GPU1.M16 GPU1.M18 GPU1.N11 GPU1.N13 GPU1.N15 GPU1.N17 GPU1.P10 GPU1.P12 GPU1.P14 GPU1.P16 GPU1.P18 GPU1.R11 GPU1.R13 GPU1.R15 GPU1.R17 GPU1.T10 GPU1.T12 GPU1.T14 GPU1.T16 GPU1.T18 GPU1.U11 GPU1.U13 GPU1.U15 GPU1.U17 GPU1.V10 GPU1.V12 GPU1.V14 GPU1.V16 GPU1.V18 PL8201.2 PL8202.2 PR8212.1 PR8309.1 PT8206.1 PT8207.1 PT8208.1
VGA_CORE_DISCHG: PQ8305.3 PR8309.2
VGA_CORE_PSI: GPU1.B4 PR8257.1
VGA_CORE_VID: GPU1.E7 PR8207.1
VGACORE_GND_SENSE_1: GPU1.F1 PR8220.2
VGACORE_VDD_SENSE_1: GPU1.F2 PR8221.2
VIDEO_CLK_XTAL_SS: GPU1.A10 R7601.1
VIDEO_THERM_OVERT#: Q7602.6 TP7606.1
VPP1: TP7801.1 VRAM1.A5
VPP2: TP7802.1 VRAM1.U5

Pads without a net: GPU1 A16 A22 AA1 AA2 AA3 AA4 AA5 AA6 AB1 AB2 AB3 AB4 AB5 AB6 AB13 AB15 AB16 AB18 AB19 AB21 AB27 AC3 AC4 AC13 AC14 AC15 AC16 AC17 AC18 AC19 AC20 AC21 AD1 AD2 AD3 AD4 AD5 AD7 AD10 AD14 AD17 AD20 AD23 AE1 AE2 AE3 AE4 AE10 AE12 AE13 AE15 AE16 AE18 AE19 AE21 AE23 AE24 AF2 AF3 AF4 AF10 AF12 AF13 AF15 AF16 AF18 AF19 AF21 AF24 AG3 AG12 AG13 AG15 AG16 AG18 AG19 AG21 AG22 AG24 AG25 B2 B3 B6 B19 C1 C2 C3 C7 C14 D4 D5 D6 D10 D11 D12 E6 E10 F4 F5 F7 F9 F10 F19 G1 G2 G3 G4 G5 G6 G7 H3 H4 H6 J1 J2 J3 J4 J5 J6 J7 K1 K2 K3 K4 K5 K6 K7 L3 L4 M1 M2 M3 M4 M5 M7 N1 N2 N3 N4 N5 N7 P3 P4 P6 P25 R1 R2 R3 R4 R5 R6 R7 T1 T2 T3 T4 T5 T6 T7 T27 U3 U4 U6 V1 V2 V3 V4 V5 V6 V7 W1 W2 W3 W4 W5 W6 W7 W22 Y3 Y4 Y6; GPU2 N1; GPU3 A1 A10 C2 D9 F9 N1; HS1 1; HS2 1; PU8301 7; PU8302 12; VRAM1 A11 A13 B11 B13 D13 E11 E13 F11 F13 M2 M4 N2 N4 P2 R2 T2 T4 U2 U4; VRAM2 A11 A13 B11 B13 D13 E11 E13 F11 F13 M2 M4 N2 N4 P2 R2 T2 T4 U2 U4; VRAM3 A11 A13 B11 B13 D13 E11 E13 F11 F13 M2 M4 N2 N4 P2 R2 T2 T4 U2 U4; VRAM4 A11 A13 B11 B13 D13 E11 E13 F11 F13 M2 M4 N2 N4 P2 R2 T2 T4 U2 U4

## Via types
v1: diameter 0.356, hole 0.178, TOP to BOTTOM, 284 vias
v2: diameter 0.508, hole 0.254, TOP to BOTTOM, 959 vias
v3: diameter 0.711, hole 0.406, TOP to BOTTOM, 268 vias

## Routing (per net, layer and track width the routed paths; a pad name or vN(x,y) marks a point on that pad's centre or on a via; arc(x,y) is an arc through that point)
3V3_AON_CT_2: length 1.7
  BOTTOM w0.203: 48.03,36.99 U8301.10
  BOTTOM w0.254: 48.03,36.99 47.87,37.15 47.87,38.04 C8306.1
3V3_AON_S0: length 204.9
  TOP w0.305: 39.61,53.55 40.06,54 40.06,54.09 40.17,54.2 RN7604.1 ; 39.61,53.55 R7617.1 39.88,52.74 RN7605.1 39.36,52.2 39.16,51.99 39.16,51.75 39.36,51.54 RN7605.2 39.88,50.57 R7649.2 ; 39.61,53.55 RN7604.2 ; C7316.1 36.44,56.56 36.44,55.44 36.52,55.36 v2(36.52,55.21)
  TOP w0.508: PR8304.1 2.8,73.27 v2(2.35,73.71) ; R7628.1 38.19,48.48 R7614.1 R7609.1 R7625.1 ; R7628.1 R7619.1 38.2,47.03 38.24,46.99 38.24,45.83 38.95,45.11 39.03,45.11 v2(39.97,44.17) 39.89,44.1 39.89,40.51 41.32,39.09 41.32,38.75 42.12,37.95 44.34,37.95 ; R7628.1 38.2,48.91 38.91,49.61 R7633.1 39.58,49.93 39.63,49.98 39.63,50.33 R7649.2 ; v2(36.52,55.21) 36.48,55.17 36.34,55.17 36.03,54.85 C7736.1 35.65,54.25 v2(35.6,54.2) 35.63,54.17 35.97,54.17 36.52,53.62 36.68,53.62 R7643.2 38.28,53.58 C7704.1 38.61,53.28 R7617.1 ; PR8258.1 34.52,8.54 v2(35.6,8.54) 36.1,9.03 PR8316.1 39.43,9.03 40.33,9.93 42.76,9.93 42.94,10.11 43.77,10.11 44.25,10.6 v2(45.94,10.6)
  L3 w0.508: v3(45.44,38.69) 45.44,38.55 45.51,38.48 45.51,34.17 45.3,33.96 45.3,30.97 45.56,30.71 45.56,10.93 45.89,10.6 v2(45.94,10.6) ; v2(8.78,73.99) 10.18,72.6 10.18,67.71 15.12,62.77 15.12,59.71 17.81,57.01 17.81,47.79 v2(18.15,47.45) 20.16,45.44 22.72,45.44 22.88,45.29 v2(23.03,45.29) ; v2(48.3,61.19) 45.96,61.19 42.33,57.56 42.33,56.54 39.55,53.76 37.15,53.76 36.71,54.2 v2(35.6,54.2)
  L6 w0.508: v2(2.35,73.71) 2.5,73.71 3.62,72.6 7.38,72.6 v2(8.78,73.99) ; v2(32.86,41.58) 32.86,41.63 v2(30.24,44.25) 30.24,42.12 29.05,40.92 v2(29.05,40.17) ; v2(27.09,6.07) 27.7,6.07 28.84,4.93 32.67,4.93 32.85,4.75 33.93,4.75 34.31,5.12 34.31,5.15 34.71,5.56 34.71,7.65 v2(35.6,8.54)
  BOTTOM w0.305: U7301.5 22.42,41.25 v2(23.26,42.09) ; RN7601.3 50.72,64.12 50.83,64.23 51.25,64.23 51.37,64.12 RN7601.4 51.63,63.62 R7657.1
  BOTTOM w0.356: GPU1.G12 36.16,55.57 v2(36.52,55.21) ; GPU1.G10 35.6,54.22 v2(35.6,54.2) ; v2(24.95,53.61) 24.58,53.98 GPU1.AA9 ; GPU1.AB8 23.64,53.11 v2(24.08,52.67) 24.5,53.09 GPU1.AA8 ; PR8203.1 26.42,6.07 v2(27.09,6.07) ; RN7601.3 49.64,62.54 49.62,62.54 v1(49.11,62.03) 48.3,61.22 v2(48.3,61.19)
  BOTTOM w0.406: v2(32.86,41.58) 32.68,41.41 Q7602.2
  BOTTOM w0.508: Q7606.G 40.08,44.07 v2(39.97,44.17) ; Q7301.G 8.13,33.73 8.13,33.73 R7303.2 8.96,34.56 8.96,34.77 9.03,34.85 9.03,40.6 8.91,40.72 8.91,45.02 8.91,45.39 11.3,47.79 16.82,47.79 17.15,47.45 v2(18.15,47.45) ; R7312.1 27.41,44.29 27.77,44.65 29.84,44.65 v2(30.24,44.25) 30.84,43.65 R7612.2 ; R7631.1 26.85,39.83 R7645.1 27.41,40.17 27.85,39.73 28.66,39.73 28.95,40.01 28.95,40.07 v2(29.05,40.17) ; PR8311.1 45.89,10.65 v2(45.94,10.6)
  vias: v1(24.68,53.01) v1(45.25,36.78) v3(44.6,38.69)
3V3_AON_S0_DISCHG: length 2.5
  TOP w0.102: v2(38.27,7.34) 38.27,7.39 38.42,7.55 PR8316.2 38.41,8.16 37.58,8.16 v1(37.48,8.26)
  BOTTOM w0.102: PQ8306.3 38.04,6.96 38.27,7.19 v2(38.27,7.34)
5V_S0: length 82.3
  TOP w0.508: v2(38.88,10.44) 39.61,10.44 41.32,12.14 41.32,19.08 42.97,20.73 v1(42.97,21.52) 42.97,31.47 44.01,32.52 v3(44.41,32.52)
  L3 w1.016: v3(8.09,43.16) 9.45,41.8 9.45,40.7 13.06,37.1 34.98,37.1 35.78,36.3 39.11,36.3 42.84,32.57 44.36,32.57 v3(44.41,32.52)
  L6 w0.508: v2(48.28,33.3) 47.67,33.91 45.81,33.91 v3(44.41,32.52)
  BOTTOM w0.203: U8301.4 48.43,33.46 v2(48.28,33.3)
  BOTTOM w0.508: PR8223.1 31.39,11.45 31.99,10.86 35.37,10.86 36.01,11.5 36.01,11.51 36.29,11.79 37.91,11.79 38.96,10.74 38.96,10.53 v2(38.88,10.44)
GND: length 338.9
  TOP w0.203: v2(18.49,89.23) 18.11,89.6 VRAM3.P10
  TOP w0.305: v2(36.13,86.58) 36.62,86.58 VRAM2.H1 ; R7632.2 39.65,58.61 40.51,57.76 v2(40.64,57.76)
  TOP w0.33: VRAM2.T10 44,80 v2(43.47,79.47) ; v2(44.39,80.4) 44.8,80.8 VRAM2.R11
  TOP w0.356: 23.19,90.8 22.8,90.41 VRAM3.R4 ; 23.19,90.8 v2(23.18,90.8) ; 23.19,90.8 23.2,90.8 VRAM3.R3 ; v2(14.39,92.43) 14.39,92.41 VRAM3.U14 ; VRAM3.T5 21.99,91.2 v2(21.58,91.61) ; VRAM3.E12 16.4,82.4 v2(16.8,82.8) ; 38.8,81.2 38.8,81.2 VRAM2.R4 39.2,80.79 39.59,80.4 v2(39.59,80.4) 39.99,80 VRAM2.T5 ; 38.8,81.2 VRAM2.R3 ; 38.8,81.2 v2(38.8,81.21) ; VRAM2.R11 44.8,80.79 v2(45.19,80.4) 45.2,80.4 VRAM2.R12 ; VRAM2.A1 36.39,92.41 v2(36.39,92.43) ; VRAM2.P10 43.45,81.05 v2(43.45,81.05) ; VRAM2.R14 47.51,80.8 47.61,80.9 v2(47.79,80.9) ; VRAM3.K14 14.8,86.4 v2(15.2,86.8) 15.2,86.8 VRAM3.K13 ; v2(38.78,92.43) 38.4,92.06 VRAM2.A3 ; VRAM3.E1 25.58,82.78 25.72,82.78 v2(25.75,82.81) ; VRAM2.U3 38.41,79.2 v2(38.81,79.6) ; VRAM3.U3 23.6,92.01 23.2,92.41 v2(23.2,92.43) ; v2(45.2,88.4) 45.6,88.8 VRAM2.E12 ; v2(16.8,88.4) VRAM3.N12 ; VRAM3.G5 21.87,84 v2(21.47,83.61) 21.88,83.2 VRAM3.F5 ; VRAM3.N14 14.35,88.8 14.29,88.74 v2(14.23,88.74) ; v2(16.8,81.21) 16.8,81.21 ; 16.8,81.21 16.8,81.19 VRAM3.C11 17.2,80.79 17.59,80.4 v2(17.59,80.4) ; 16.8,81.21 VRAM3.C12 VRAM3.C13 ; VRAM2.L5 40.38,83.62 v2(40.53,83.62) ; VRAM2.M10 43.88,83.2 v2(43.47,83.61) 43.87,84 VRAM2.L10 ; VRAM3.A3 23.24,78.84 23.23,78.84 v2(23.15,78.77) ; 37.2,85.21 37.2,85.2 36.8,84.8 VRAM2.K1 ; 37.2,85.21 37.6,84.81 VRAM2.K2 ; 37.2,85.21 v2(37.2,85.22) ; v2(40.4,88.4) 40.01,88 VRAM2.F5 ; VRAM3.M10 18.01,88 v2(18.4,88.4) ; v2(25.84,92.1) 25.3,92.1 VRAM3.U1 ; VRAM2.G5 40.02,87.2 v2(40.43,87.61) ; v2(23.18,80.39) 23.59,80.8 VRAM3.C3 ; VRAM3.D10 18.04,81.6 v2(18.43,81.21) ; VRAM2.C13 VRAM2.C14 47.54,90.4 v2(47.8,90.66) ; VRAM2.A12 45.6,92.01 45.2,92.41 v2(45.2,92.43) ; VRAM3.H14 14.8,84.8 15.2,85.2 15.2,85.21 ; v2(21.55,87.58) 21.58,87.58 21.96,87.2 VRAM3.L5 ; v2(25.81,90.55) 25.66,90.4 VRAM3.R1 ; VRAM3.F10 18.41,82.79 v2(18.41,82.78) ; VRAM2.C1 36.54,90.4 36.33,90.61 36.19,90.61 v2(36.13,90.66) ; VRAM3.G10 18.39,83.61 v2(18.41,83.61) ; VRAM3.R14 14.54,90.4 14.33,90.61 14.19,90.61 v2(14.13,90.66) ; VRAM2.N1 36.77,82.4 36.34,81.97 v2(36.26,81.97) ; v2(45.15,78.77) 45.23,78.84 45.24,78.84 VRAM2.U12 ; VRAM3.E3 23.6,82.4 v2(23.2,82) ; v2(37.2,86.8) 37.2,86.8 VRAM2.H2 ; VRAM2.C3 38.44,90.4 38.82,90.78 v2(38.82,90.8) 38.84,90.78 38.84,90.76 VRAM2.C4 ; VRAM3.K1 25.2,86.4 v2(24.8,86) VRAM3.K2 ; v2(14.39,78.79) 14.79,79.2 VRAM3.A14 ; v2(33.16,65.17) 32.46,64.47 C7505.2 ; VRAM2.U1 36.79,79.2 v2(36.39,78.79) ; VRAM2.B10 43.97,91.2 43.62,91.54 v2(43.58,91.54) ; VRAM3.C14 14.8,80.78 14.26,80.24 v2(14.26,80.22) ; VRAM3.R12 16.44,90.4 16.82,90.78 v2(16.82,90.8) 16.84,90.78 16.84,90.76 VRAM3.R11 ; v2(25.51,78.71) 25.51,78.89 VRAM3.A1 ; VRAM2.E14 48.06,88.8 v2(48.16,88.91) ; VRAM3.U12 16.4,92.06 v2(16.78,92.43) ; VRAM2.H13 v2(46.8,86) 47.2,86.4 VRAM2.H14 ; v2(23.2,88.4) 23.6,88.8 VRAM3.N3 ; VRAM3.N1 v2(25.79,88.8) ; v2(44.4,88.4) 44,88 VRAM2.F10 ; VRAM3.H2 24.4,84.79 v2(24.78,84.41) 24.81,84.41 VRAM3.H1 ; VRAM2.T10 44,80 v2(44.39,80.4) ; v2(18.43,87.61) 18.02,87.2 VRAM3.L10 ; v2(45.2,82) 45.6,82.4 VRAM2.N12 ; v2(18.41,79.63) 18.37,79.63 VRAM3.B10 ; v2(14.26,81.97) 14.34,81.97 14.77,82.4 VRAM3.E14 ; VRAM2.N14 47.4,82.6 48.21,82.6 v2(48.5,82.31) ; VRAM2.C11 45.18,90.78 v2(45.18,90.79) 45.21,90.79 VRAM2.C12 ; VRAM2.R1 36.8,80.78 36.26,80.24 v2(36.26,80.22) ; VRAM2.D10 43.65,89.6 v2(43.33,89.93) ; VRAM3.C4 22.42,80.42 v2(22.39,80.42) ; VRAM2.U14 47.28,79.2 47.67,78.81 v2(47.75,78.81) ; VRAM2.B5 39.98,91.2 v2(39.59,90.81) ; VRAM2.A14 47.3,92.1 v2(47.84,92.1) ; v2(16.82,79.6) 16.42,79.2 VRAM3.A12 ; VRAM2.N3 38.4,82.4 v2(38.8,82.8) ; v2(17.59,90.81) 17.98,91.2 VRAM3.T10 ; VRAM2.K13 VRAM2.K14 47.49,84.8 v2(47.74,84.55) ; VRAM3.C1 25.37,80.8 v2(25.75,80.43) ; v2(43.43,87.17) 43.45,87.2 VRAM2.G10 ; VRAM3.H13 15.6,84.81 15.2,85.21 ; v2(22.4,88.4) 22,88 VRAM3.M5 ; VRAM2.E1 v2(36.16,88.8) ; v2(40.53,82.83) 40.48,82.83 40.11,83.2 VRAM2.M5 ; 15.2,85.21 v2(15.2,85.22) ; v2(21.61,79.61) VRAM3.B5 ; v2(38.8,88.4) VRAM2.E3
  TOP w0.457: v2(34.82,50.2) 34.82,50.47 34.81,50.48 34.81,50.85 34.11,51.55 C7605.2
  TOP w0.508: v2(34.82,50.2) 35.33,49.69 C7703.2 ; R7811.1 C7817.2 31.92,83.24 v2(31.89,83.21) ; v2(29.81,62.51) 29.76,62.56 29.63,62.56 29.05,63.15 C7513.2 ; C7923.2 29.98,80.14 30.16,79.96 v2(30.77,79.96) ; C7805.2 32.34,80.31 C7816.2 v2(31.59,81.16) ; R7810.1 50.35,92.17 v2(49.88,92.64) ; C7605.2 34.88,51.9 34.9,51.87 C7728.2 C7729.2 ; v2(8.17,35.66) 8.17,35.61 8.48,35.3 8.48,34.35 EC9701.2 ; v2(23.22,62.65) 23.46,62.9 23.46,62.91 23.69,63.14 C7520.2 ; C7819.2 31.41,91.06 v2(31.23,91.24) ; C7712.2 33.07,52.61 C7711.2 33.14,52.85 33.14,53.43 v2(33.02,53.55) 32.39,53.55 C7713.2 ; C7804.2 32.34,78.22 C7815.2 32.31,79.05 v2(31.69,79.05) ; C7806.2 v2(31.26,82.2) ; C7907.2 v2(30.75,94.03) ; v2(35.07,3.08) 35.37,3.08 35.69,3.39 C8308.1 ; v2(37.38,52.71) 37.56,52.53 37.64,52.53 37.9,52.28 C7704.2 ; v2(32.91,62.56) 32.99,62.56 33.66,63.23 33.66,63.29 C7514.2 ; EC9702.2 0.85,31.68 ; C7921.2 30.39,82.43 v2(30.54,82.58) 30.54,83.19 30.16,83.57 C7918.2 ; v2(21.63,60.16) 21.84,59.95 C7323.2 ; R7518.2 33.31,50.31 v2(33.2,50.2) ; C7909.2 v2(30.21,90.81) ; v2(18.89,63.78) 18.89,63.81 19.29,64.21 R7301.2 ; v2(45.58,6.38) 44.03,7.93 C8309.2 ; v2(41.01,65.73) 41.29,65.73 41.49,65.93 R7506.2 R7507.1 ; C7911.2 30.26,88.52 30.41,88.67 v2(30.62,88.67) 30.36,88.93 30.36,89.19 C7915.2 ; C7906.2 30.86,79 v2(30.86,78.99) ; C7818.2 v2(31.36,93.35) ; v2(30.95,84.61) 30.84,84.71 C7922.2 ; v2(19.37,68.61) 20.84,67.14 C7326.2 ; PC8205.2 28.65,5.99 v2(29.23,6.56) ; v2(30.55,87.63) 30.52,87.66 R7911.1 ; v2(39,56.01) 39.16,56.18 R7602.2 R7621.2 ; v2(31.46,86.49) 31.46,86.49 C7824.2 ; C7809.2 31.67,89.92 31.64,89.94 v2(31.18,89.94) ; C7807.2 v2(31,92.2) ; C7925.2 C7926.2 10.65,77.5 v2(10.65,76.81) ; PR8259.2 PC8226.1 34.34,5.78 33.95,5.39 v2(33.67,5.39) ; v2(30.81,81.24) 30.81,81.24 30.76,81.28 C7905.2 ; C7318.2 23.57,57.71 24.03,57.71 v2(24.07,57.68) ; v2(35.65,67.6) 36.19,68.13 C7525.2 ; C7820.2 31.61,88.77 v2(31.46,88.62) 31.46,88.01 31.84,87.63 C7813.2 ; C7507.2 31.44,62.84 v2(31.77,62.51) ; C8310.2 38.69,6.65 38.78,6.73 v2(39,6.73) ; R7607.1 37.38,50.92 37.38,50.24 v2(37.33,50.19) 38.1,50.19 R7610.2 ; v2(30.47,92.94) 30.42,92.99 C7920.2 29.7,92.27 C7904.2 ; C7910.2 v2(30.64,77.85)
  BOTTOM w0.127: R7629.2 38.81,43.06
  BOTTOM w0.152: GPU1.AF8 20.54,53.14 20.97,53.57 v2(21.58,53.57)
  BOTTOM w0.203: v2(39,56.01) 39.6,56.01 39.99,55.62 GPU1.B11 ; v2(18.49,89.23) 18.11,89.6 VRAM3.P10 ; PU8302.18 v2(48.17,18.14) ; v2(48.38,37.44) 48.43,37.39 U8301.11
  BOTTOM w0.254: v2(24.83,5.38) 24.83,5.9 PC8222.2 ; v2(37.63,46.74) 37.63,47.15 37.65,47.16 37.65,48.1 GPU1.E2 ; GPU1.AB17 23.39,60.58 23.21,60.76 v2(23.21,61.04)
  BOTTOM w0.279: v2(33.2,67.57) 33.19,67.57 32.82,67.2 GPU1.L25 ; GPU1.P23 30.67,65.23 v2(30.67,65.18) ; GPU1.L5 32.8,50.6 v2(33.2,50.2) ; v2(35.65,67.6) 35.57,67.51 35.57,67.51 GPU1.H25 ; v2(40.64,57.76) 40.56,57.76 40.22,58.1 GPU1.B14 ; v2(27.4,51.03) 27.82,50.61 GPU1.U5 ; v2(27.98,69.27) 27.89,69.18 27.89,68.07 GPU1.U26 ; GPU1.AG2 19.44,48.04 19.44,47.25 v2(19.45,47.25) 19.45,47.25 20.25,47.25 GPU1.AF1 ; GPU1.H23 35.4,65.46 35.4,65.41 v2(35.64,65.17) ; v2(41.57,62.97) 40.62,62.97 40.59,63 40.53,63.06 GPU1.B20 ; GPU1.AF23 20.38,65.55 v2(19.96,65.13) ; GPU1.A26 41,68.15 41.25,68.4 41.25,68.81 40.88,69.18 v2(40.88,69.42) 40.57,69.1 40.55,69.1 40.24,68.8 GPU1.B27 ; GPU1.AD21 v2(21.6,64.3) GPU1.AD22 GPU1.AC22 ; GPU1.E22 37.42,64.32 v2(37.33,64.32) ; GPU1.Y23 25.33,65.6 v2(24.91,66.02) ; GPU1.AE14 21.2,58.12 v2(20.8,58.52) 20.4,58.12 GPU1.AF14 ; v2(22.45,47.76) 22.45,47.76 22.85,48.16 GPU1.AC2 ; v2(41.01,65.73) 40.98,65.71 40.67,65.71 40.52,65.55 GPU1.B23 ; GPU1.AB11 23.64,55.63 v2(23.23,56.04) ; v2(30.27,68.56) 30.3,68.52 GPU1.P26 ; GPU1.U23 27.82,65.55 v2(27.42,65.15) ; v2(22.7,69.42) 22.7,68.23 22.85,68.07 GPU1.AC26 ; GPU1.L23 32.92,65.46 32.92,65.41 v2(33.16,65.17) ; GPU1.AA7 24.37,52.17 23.77,52.17 GPU1.AB7 v2(23.22,52.72) GPU1.AC8 ; v2(25.75,50.19) GPU1.Y5 ; v2(29.9,47.76) 29.9,47.78 30.3,48.17 GPU1.P2 ; v2(32.22,46.89) 32.37,47.04 32.37,47.79 GPU1.L2 ; GPU1.Y2 v2(25.74,47.8) ; GPU1.E20 38.17,62.69 v2(38.17,62.64) ; GPU1.AB24 24.09,66.01 24.09,66 v2(24.1,65.99) ; v2(27.39,47.8) 27.5,47.91 27.53,47.91 GPU1.U2
  BOTTOM w0.305: GPU3.B7 5.95,58.42 v2(6.04,58.5) ; v2(41.42,50.57) 41.32,50.57 41.24,50.65 GPU1.B5 ; GPU1.AC5 22.85,50.63 22.47,50.24 v2(22.42,50.24) ; v2(7.97,58.47) 7.97,58.04 7.75,57.83 GPU3.B10 ; v2(4.1,58.5) 4.15,58.45 GPU3.B4 ; 19.66,43.87 20.02,43.51 U7301.3 ; v2(47.84,92.1) 47.3,92.1 VRAM2.A14 ; RN301.4 46.67,52.51 v2(46.7,52.48) 46.73,52.51 46.73,52.88 46.45,53.16 RN301.3 ; GPU3.A2 2.95,59.95 v2(2.76,60.15) ; v2(37.37,60.18) 37.78,60.58 GPU1.E17 ; GPU1.Y26 25.34,68.18 25.43,68.26 25.43,69.36 v2(25.37,69.41) ; v2(6.56,50.17) 6.55,50.17 GPU3.F8 ; v2(4.76,50.14) 4.76,51 GPU3.F5 ; GPU3.B1 2.35,57.99 2.2,58.14 2.2,58.45 v2(2.17,58.47) ; GPU3.F2 2.95,49.07 v2(2.94,49.05) ; v2(43.32,9.45) 43.32,9.07 43.54,8.85 PQ8307.4 ; v2(4.76,60.11) 4.75,60.1 GPU3.A5 ; v2(8.32,52.81) 8.3,52.81 8.18,52.7 7.81,52.7 7.81,52.7 GPU3.E10 ; v2(21.59,58.51) 22,58.91 GPU1.AD15 ; GPU1.E14 37.4,57.7 37.39,57.7 v2(37.36,57.68) ; GPU1.AD16 22,59.78 21.66,60.13 21.66,60.13 v2(21.63,60.16) ; v2(29.89,50.22) 29.91,50.25 29.91,50.27 30.24,50.6 GPU1.P5 ; VRAM3.U1 25.3,92.1 v2(25.84,92.1) ; v2(6.04,51.84) 5.95,51.92 GPU3.E7 ; GPU1.B8 40.25,53.14 40.41,52.99 41.39,52.99 41.43,52.95 v2(41.46,52.95) ; GPU1.B17 40.53,60.58 40.62,60.49 41.36,60.49 v2(41.4,60.45) ; GPU3.E1 2.26,52.7 2.07,52.89 v2(1.79,52.89) ; RN7602.1 14.07,48.67 13.88,48.86 13.88,49.12 14.09,49.33 RN7602.2 14.61,49.77 v2(14.8,49.97) ; GPU1.E25 38.14,67.59 v2(38.17,67.59)
  BOTTOM w0.33: v2(44.39,80.4) 44.8,80.8 VRAM2.R11 ; v2(36.26,81.97) 36.37,81.97 VRAM2.N1 ; v2(14.26,81.97) 14.37,81.97 VRAM3.E14 ; VRAM2.A12 45.6,92.01 45.2,92.41 v2(45.2,92.43) ; VRAM3.U3 23.6,92.01 23.2,92.41 v2(23.2,92.43)
  BOTTOM w0.356: v2(39.59,90.81) 39.98,91.2 VRAM2.B5 ; VRAM3.M5 22,88 v2(22.4,88.4) ; v2(21.55,87.58) 21.58,87.58 21.96,87.2 VRAM3.L5 ; VRAM3.T10 17.98,91.2 v2(17.59,90.81) ; v2(48.16,88.91) 48.15,88.89 47.88,88.89 47.79,88.8 VRAM2.E14 ; v2(18.4,88.4) 18.01,88 VRAM3.M10 ; VRAM3.A12 16.42,79.2 v2(16.82,79.6) ; GPU1.AD12 22,56.49 21.62,56.87 v2(21.6,56.87) 21.62,56.88 21.67,56.88 22,57.21 GPU1.AD13 ; VRAM3.D10 18.04,81.6 v2(18.43,81.21) ; v2(14.13,90.66) 14.33,90.46 14.74,90.46 VRAM3.R14 VRAM4.C13 ; v2(21.58,91.61) 21.99,91.2 VRAM3.T5 ; VRAM2.C4 39.18,90.4 38.82,90.77 v2(38.82,90.8) 38.42,90.4 VRAM2.C3 ; v2(38.8,82.8) 38.4,82.4 VRAM2.N3 ; v2(16.8,82.8) 16.4,82.4 VRAM3.E12 ; GPU1.AG26 19.62,68.02 19.62,68.35 v2(19.37,68.61) ; 15.2,85.2 14.8,84.8 VRAM3.H14 ; 15.2,85.2 15.2,85.2 VRAM3.H13 ; 15.2,85.2 v2(15.2,85.22) ; 38.8,81.2 38.8,81.2 VRAM2.R4 39.2,80.79 v2(39.59,80.4) 39.99,80 VRAM2.T5 ; 38.8,81.2 VRAM2.R3 ; 38.8,81.2 v2(38.8,81.21) ; v2(44.4,88.4) 44,88 VRAM2.F10 ; v2(16.78,92.43) 16.4,92.06 VRAM3.U12 ; GPU1.AE11 21.2,55.63 v2(20.79,56.04) 20.4,55.64 GPU1.AF11 ; VRAM2.P10 43.45,81.05 v2(43.45,81.05) ; VRAM2.K2 37.6,84.81 37.2,85.21 ; VRAM3.E1 25.58,82.78 25.72,82.78 v2(25.75,82.81) ; GPU1.AD19 22.33,61.89 v2(22.4,61.82) 22,61.43 GPU1.AD18 ; VRAM2.H1 36.38,86.4 36.2,86.58 v2(36.13,86.58) ; GPU1.AB20 23.63,63.06 v2(23.22,62.65) ; v2(47.75,78.81) 47.67,78.81 47.28,79.2 VRAM2.U14 ; v2(44.39,80.4) 44,80 VRAM2.T10 44,80 v2(43.47,79.47) ; VRAM3.L10 18.02,87.2 v2(18.43,87.61) ; GPU1.E11 38.21,55.21 v2(38.21,55.18) ; VRAM2.H2 37.6,86.4 v2(37.2,86.8) ; v2(22.39,80.42) 22.42,80.42 VRAM3.C4 ; v2(16.8,88.4) VRAM3.N12 ; v2(21.61,79.61) VRAM3.B5 ; VRAM3.N14 14.35,88.8 14.29,88.74 v2(14.23,88.74) ; VRAM3.C11 17.2,80.81 v2(16.8,81.21) 16.4,80.8 VRAM3.C12 ; v2(25.75,80.43) 25.37,80.8 VRAM3.C1 ; VRAM2.A1 36.39,92.41 v2(36.39,92.43) ; VRAM2.M10 43.88,83.2 v2(43.47,83.61) 43.87,84 VRAM2.L10 ; v2(40.22,46.18) 40.22,47.04 40.2,47.07 GPU1.B1 ; v2(23.18,80.39) 23.59,80.8 VRAM3.C3 ; VRAM3.R11 17.18,90.4 16.82,90.77 v2(16.82,90.8) 16.42,90.4 VRAM3.R12 ; v2(45.2,82) 45.6,82.4 VRAM2.N12 ; GPU1.E8 37.8,53.13 v2(37.38,52.71) ; v2(45.2,88.4) 45.6,88.8 VRAM2.E12 ; VRAM3.C14 14.8,80.78 14.26,80.24 v2(14.26,80.22) ; VRAM2.F5 40.01,88 v2(40.4,88.4) ; VRAM2.R11 44.8,80.79 v2(45.19,80.4) 45.58,80.8 VRAM2.R12 ; VRAM2.N14 47.4,82.6 48.21,82.6 v2(48.5,82.31) ; VRAM2.C14 47.51,90.4 47.67,90.57 47.71,90.57 v2(47.8,90.66) ; v2(14.39,92.43) 14.39,92.41 VRAM3.U14 ; VRAM2.D10 43.65,89.6 v2(43.33,89.93) ; v2(40.83,47.63) 41,47.79 GPU1.A2 ; v2(14.39,78.79) 14.79,79.2 VRAM3.A14 ; v2(23.2,88.4) 23.6,88.8 VRAM3.N3 ; VRAM3.R1 25.44,90.4 25.52,90.48 25.73,90.48 v2(25.81,90.55) ; v2(23.15,78.77) 23.58,79.2 VRAM3.A3 ; v2(47.79,80.9) 47.61,80.9 47.51,80.8 VRAM2.R14 47.09,80.69 46.51,80.69 VRAM1.C13 ; v2(36.39,78.79) 36.79,79.2 VRAM2.U1 ; v2(38.81,79.6) 38.41,79.2 VRAM2.U3 ; VRAM2.C11 44.8,90.41 45.18,90.79 v2(45.18,90.79) 45.21,90.79 VRAM2.C12 ; v2(40.53,83.62) 40.38,83.62 VRAM2.L5 ; VRAM3.K1 25.2,86.4 v2(24.8,86) VRAM3.K2 ; GPU1.E5 37.75,50.62 v2(37.33,50.19) ; v2(35.12,47.55) 35.26,47.69 GPU1.H2 ; 23.19,90.8 23.2,90.8 VRAM3.R3 ; 23.19,90.8 23.19,90.79 VRAM3.R4 ; 23.19,90.8 v2(23.18,90.8) ; VRAM2.C1 36.74,90.46 36.33,90.46 v2(36.13,90.66) ; VRAM3.N1 v2(25.79,88.8) ; VRAM3.G10 18.39,83.61 v2(18.41,83.61) ; v2(45.15,78.77) 45.58,79.2 VRAM2.U12 ; v2(24.07,57.68) 24.07,57.74 23.71,58.1 GPU1.AB14 ; VRAM2.H14 47.2,86.4 v2(46.8,86) VRAM2.H13 ; v2(25.51,78.71) 25.51,78.89 VRAM3.A1 ; VRAM3.H1 24.81,84.41 v2(24.78,84.41) 24.4,84.79 VRAM3.H2 ; VRAM3.F10 18.41,82.79 v2(18.41,82.78) ; VRAM2.K13 46.78,84.8 46.79,84.78 47.18,84.78 VRAM2.K14 47.23,84.77 47.52,84.77 v2(47.74,84.55) ; VRAM2.G5 40.02,87.2 v2(40.43,87.61) ; VRAM3.E3 23.6,82.4 v2(23.2,82) ; GPU1.AE17 21.2,60.53 v2(20.81,60.14) 20.4,60.54 GPU1.AF17 ; VRAM3.K14 14.8,86.4 v2(15.2,86.8) 15.6,86.4 VRAM3.K13 ; 37.2,85.21 37.2,85.2 VRAM2.K1 ; 37.2,85.21 v2(37.2,85.22) ; v2(38.78,92.43) 38.4,92.06 VRAM2.A3 ; GPU1.AE20 GPU1.AF20 19.79,63.06 v2(19.73,63) ; VRAM3.F5 21.88,83.2 v2(21.47,83.61) 21.87,84 VRAM3.G5 ; GPU1.AF5 20.02,50.27 v2(18.91,50.27) ; v2(38.8,88.4) VRAM2.E3 ; v2(18.41,79.63) 18.37,79.63 VRAM3.B10 ; VRAM2.E1 v2(36.16,88.8) ; v2(43.58,91.54) 43.62,91.54 43.97,91.2 VRAM2.B10 ; v2(34.82,50.2) 35.22,50.6 GPU1.H5 ; v2(40.53,82.83) 40.48,82.83 40.11,83.2 VRAM2.M5 ; VRAM2.G10 43.45,87.2 v2(43.43,87.17) ; VRAM2.R1 36.8,80.78 36.26,80.24 v2(36.26,80.22)
  BOTTOM w0.406: PQ8305.1 36.52,8.31 v2(36.95,7.88) ; v2(37.1,2.42) 37.05,2.37 36.15,2.37 PQ8301.1 ; PQ8308.1 50.69,51.48 50.69,51.4 v2(50.62,51.34) ; v2(38.14,10.41) 38.14,10.35 38.39,10.1 38.39,9.82 ; PQ8307.1 41.85,7.15 41.27,6.57 v2(41.27,6.35) ; v2(52.8,51.06) 52.56,50.82 PQ8308.4 ; PQ8306.4 39.02,6.75 v2(39,6.73) ; v2(38.98,3.51) 38.84,3.65 PQ8301.4
  BOTTOM w0.508: PC8221.1 19.69,18.93 v2(19.5,19.13) ; X7601.2 48.38,55.26 49.13,55.26 49.14,55.25 v2(49.16,55.25) ; v2(17.14,59.19) 16.91,59.41 C7317.2 15.45,59.41 C7319.2 ; R7615.2 R7611.2 R7608.2 38.05,43.06 38.81,43.06 ; R7615.2 36.3,43.06 C7606.2 36.87,42.22 36.92,42.17 v2(36.95,42.17) ; R7615.2 R7626.2 ; PC8301.2 4.92,80.5 v2(4.84,80.57) ; v2(34.28,73.71) 34.76,73.23 R7521.1 R7520.1 ; PC8304.2 v2(8.17,68.25) ; v2(47.36,51.62) 47.36,51.74 47.35,51.76 R7627.2 ; PC8206.2 30.77,12.79 v3(30.77,13.52) ; R7637.2 46.75,58.7 v2(46.83,58.63) 46.83,57.56 X7601.4 ; PC8217.2 PR8213.2 v2(22.02,7.92) ; PC8225.1 33.37,6.06 33.04,5.72 v2(33.04,5.46) ; PC8306.2 PC8307.2 9.69,76 v2(9.44,75.75) ; C8302.2 C8306.2 47.92,39.3 47.57,39.65 v2(47.55,39.65) ; v3(19.7,44.71) 19.66,44.67 R7306.2 19.66,43.87 ; v2(14.77,58.73) 15.34,58.16 R7302.2 ; v2(3.83,75.09) 3.83,75.03 3.39,74.6 PR8313.2 3.22,74.54 PC8302.2 ; v2(45.84,53.95) 45.41,54.38 R7601.2 ; v2(31.93,9.66) 31.92,9.67 31.92,9.87 31.65,10.14 31.63,10.14 31.39,10.38 PR8224.2 ; PR8323.1 PC8316.2 43.47,12.12 v2(43.14,12.45) ; v2(42.76,19) 43.02,19 43.14,18.88 43.42,18.88 PC8317.2 ; v2(14.09,64.82) 14.09,64.76 C7506.2 15.42,64.57 C7518.2 ; PR8302.2 v2(4.1,79.51) ; EC9703.2 26.6,3.38 PC8202.1 27.36,3.88 v2(27.6,4.12) ; v2(43.14,16.06) 43.22,16.06 43.6,15.68 PR8326.2 PC8318.2 ; C7610.2 27.41,38.97 27.41,38.05 v2(27.47,37.99) ; C7310.2 v2(11.52,59.59) ; C7609.2 27.12,41.2 26.76,41.56 v2(26.76,41.81) ; v3(29,13.52) 28.86,13.38 PC8218.2 ; v2(32.96,44.81) 32.91,44.76 C7603.2 C7604.2 ; PC8207.2 28.71,11.45 28.03,10.77 v2(28.03,9.66)
  vias: v1(1.23,86.26) v1(1.36,85.96) v1(1.69,62.39) v1(1.97,76.89) v1(2.68,45.34) v1(3.29,62.03) v1(4.21,28.78) v1(7.58,86.06) v1(8.14,62.54) v1(8.45,95.1) v1(10.45,33.18) v1(10.79,94.87) v1(26.84,49.84) v1(28.74,49.58) v1(40.66,1.25) v1(52.11,14.41) v1(52.31,57.1) v1(52.31,51.84) v1(52.54,33.2) v1(52.9,94.47) v1(52.92,7.95) v1(53.15,27.28) v1(53.13,17.33) v1(53.2,66.22) v1(53.25,8.61) v1(53.36,87.18) v1(53.33,81.05) v1(53.46,78.06) v1(53.41,29.52) v1(53.81,94.44) v2(0.76,85.25) v2(0.76,83.22) v2(0.76,81.18) v2(0.76,79.15) v2(0.76,77.12) v2(0.76,75.09) v2(0.76,73.06) v2(0.76,71.02) v2(0.76,68.99) v2(0.76,66.96) v2(0.76,64.93) v2(0.76,62.9) v2(0.76,60.86) v2(0.76,58.83) v2(0.78,57.36) v2(0.76,50.7) v2(0.76,48.67) v2(0.76,46.64) v2(0.76,44.61) v2(0.76,42.58) v2(0.76,40.54) v2(0.76,38.51) v2(0.76,36.48) v2(0.76,34.45) v2(0.76,32.42) v2(0.78,30.97) v2(1.87,61.09) v2(1.95,95.46) v2(2.15,63.33) v2(3.12,28.26) v2(4,51.79) v2(4.59,74.1) v2(4.94,95.74) v2(5.15,28.26) v2(5.27,74.1) v2(5.98,74.1) v2(6.37,60.1) v2(6.67,74.1) v2(7.18,28.26) v2(8.3,79.4) v2(8.58,95.71) v2(8.59,88.01) v2(8.68,82.58) v2(9.13,94.24) v2(9.18,84.41) v2(9.16,83.44) v2(9.24,92.18) v2(9.21,90.38) v2(9.29,89.03) v2(9.26,86.92) v2(9.21,86.06) v2(9.21,85.22) v2(9.26,28.27) v2(9.31,93.2) v2(11,95.74) v2(11.22,54.11) v2(11.22,27.16) v2(11.37,49.33) v2(11.6,51.72) v2(11.52,51.03) v2(11.6,50.22) v2(11.76,25.29) v2(11.76,23.26) v2(11.76,21.22) v2(11.76,19.19) v2(11.78,15.83) v2(12.87,54.94) v2(13.04,95.74) v2(13.02,50.32) v2(13.25,14.06) v2(13.81,51.64) v2(14.26,54.97) v2(15.07,95.74) v2(15.29,14.06) v2(15.53,53.78) v2(16.8,52.86) v2(16.83,51.01) v2(17.1,95.74) v2(17.32,14.06) v2(19.13,95.74) v2(19.92,58.46) v2(20.46,13.06) v2(21.06,10.25) v2(21.12,8.46) v2(21.12,5.79) v2(21.5,4.07) v2(23.2,95.74) v2(23.15,3.76) v2(25.23,95.74) v2(25.31,3.18) v2(26.59,51.04) v2(26.82,61.6) v2(26.86,59.64) v2(26.88,57.65) v2(26.89,55.55) v2(26.91,0.77) v2(27.26,95.74) v2(27.78,62.54) v2(27.8,54.44) v2(28.77,61.58) v2(28.8,57.59) v2(28.77,55.61) v2(28.82,59.69) v2(29.29,95.74) v2(29.71,0.77) v2(29.81,54.46) v2(29.84,7.17) v2(29.84,5.95) v2(30.44,6.56) v2(30.8,61.58) v2(30.8,59.67) v2(30.8,57.64) v2(30.81,55.62) v2(31.32,95.74) v2(31.82,54.46) v2(32.78,59.67) v2(32.78,57.64) v2(32.79,55.58) v2(32.81,61.6) v2(33.13,0.76) v2(33.36,95.74) v2(33.77,54.49) v2(34.79,55.71) v2(34.83,57.57) v2(34.94,59.62) v2(35.39,95.74) v2(37.18,0.77) v2(37.42,95.74) v2(39.45,95.74) v2(41.26,0.76) v2(41.48,95.74) v2(43.29,0.76) v2(43.52,95.74) v2(45.55,95.74) v2(45.86,56.1) v2(47.36,53.8) v2(48.17,15.68) v2(48.43,35.36) v2(51.41,94.85) v2(51.76,31.27) v2(53.48,95.13) v2(54.11,12.58) v2(54.24,91.82) v2(54.22,89.84) v2(54.24,87.76) v2(54.24,85.73) v2(54.22,83.26) v2(54.22,79.94) v2(54.22,77.4) v2(54.24,75.57) v2(54.24,73.54) v2(54.24,71.5) v2(54.24,69.47) v2(54.24,67.44) v2(54.24,65.41) v2(54.24,63.38) v2(54.24,61.34) v2(54.24,59.31) v2(54.24,57.28) v2(54.24,55.25) v2(54.24,53.22) v2(54.24,51.18) v2(54.24,49.15) v2(54.24,47.12) v2(54.24,45.09) v2(54.24,43.06) v2(54.24,41.02) v2(54.24,38.99) v2(54.24,36.96) v2(54.24,34.93) v2(54.24,32.9) v2(54.24,30.86) v2(54.24,28.83) v2(54.24,26.8) v2(54.24,24.77) v2(54.24,22.74) v2(54.24,20.7) v2(54.24,18.67) v2(54.24,16.64) v2(54.24,14.61) v2(54.24,8.51) v3(3.32,47.3) v3(3.72,46.36) v3(4.51,47.3) v3(4.61,46.41) v3(5.58,46.38) v3(10.56,36.26) v3(10.58,35.37) v3(10.61,37.15) v3(10.61,34.48) v3(11.37,36.5) v3(11.36,35.65) v3(11.38,34.81) v3(13.55,21.42) v3(13.55,20.48) v3(13.53,19.41) v3(13.53,18.47) v3(13.53,17.45) v3(13.55,16.41) v3(13.55,15.45) v3(29,17.98) v3(29,17.07) v3(29,16.2) v3(29,15.29) v3(29,14.43) v3(29.89,17.96) v3(29.89,17.07) v3(29.89,16.18) v3(29.89,15.29) v3(29.89,14.41) v3(29.89,13.52) v3(30.77,17.96) v3(30.77,17.07) v3(30.77,16.18) v3(30.77,15.29) v3(30.77,14.41) v3(37.56,34.9) v3(37.76,37.39) v3(38.47,34.9) v3(38.65,37.39) v3(39.54,37.36) v3(40.38,37.34) v3(41.85,26.93) v3(41.82,26.06) v3(41.85,25.2) v3(41.85,24.31) v3(41.85,23.42) v3(41.85,22.56) v3(42.43,37.21) v3(42.43,36.3) v3(42.43,34.5) v3(42.59,17.99) v3(42.59,16.59) v3(42.56,15.45) v3(42.59,14.1) v3(42.59,13.19) v3(42.56,10.77) v3(44.01,35.89) v3(44.03,35.06) v3(44.06,34.15) v3(47.87,10.06) v3(48.15,12.73) v3(48.86,10.04) v3(53.28,35.11) v3(53.3,34.19) v3(53.3,33.35)
